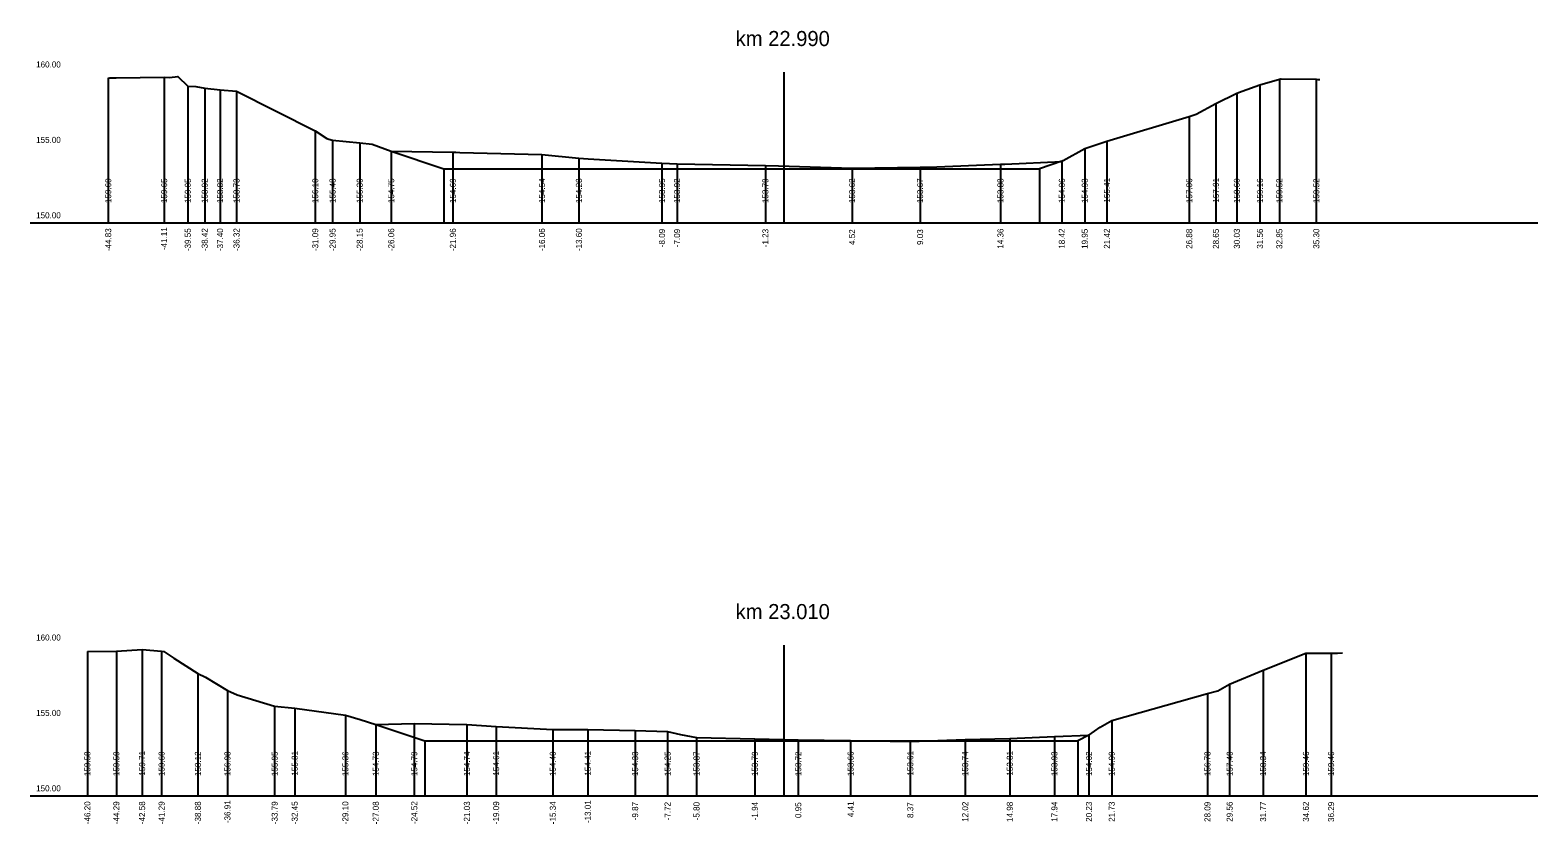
# Model space of a CAD drawing. Extents: x -582678 to -581845, y -1210354 to -1210235.
# Drawn here: x -582275.4 to -582175.4, y -1210306.7 to -1210254.1 of the extents above; entities that cross this region are included whole.
import ezdxf

# ---------------------------------------------------------------- set-up
doc = ezdxf.new("R2010")
doc.units = 0
for name, color, linetype in [('_N_osa', 7, 'Continuous'), ('_N_pomocná', 7, 'Continuous'), ('_N_tučná', 7, 'Continuous'), ('_S_popis', 7, 'Continuous'), ('_S_popis_oprav!', 7, 'Continuous'), ('_S_tenká', 7, 'Continuous'), ('_S_velmi_tenká', 7, 'Continuous')]:
    doc.layers.add(name, color=color, linetype=linetype)

msp = doc.modelspace()

# ---------------------------------------------------------------- linework, layer by layer
at = {"layer": '_N_osa'}
for p, q in [((-582225.45, -1210256.87), (-582225.45, -1210266.87)), ((-582225.45, -1210294.87), (-582225.45, -1210304.87))]:
    msp.add_line(p, q, dxfattribs=at)
at = {"layer": '_N_pomocná'}
for p, q in [((-582248, -1210263.29), (-582248, -1210266.87)), ((-582208.51, -1210263.29), (-582208.51, -1210266.87)), ((-582249.27, -1210301.23), (-582249.27, -1210304.87)), ((-582205.95, -1210301.23), (-582205.95, -1210304.87))]:
    msp.add_line(p, q, dxfattribs=at)
at = {"layer": '_N_tučná'}
for p, q in [((-582251.5, -1210262.12), (-582248, -1210263.29)), ((-582207.02, -1210262.79), (-582208.51, -1210263.29)), ((-582252.52, -1210300.14), (-582249.27, -1210301.23)), ((-582205.22, -1210300.85), (-582205.95, -1210301.23))]:
    msp.add_line(p, q, dxfattribs=at)
for points in [[(-582248, -1210263.29), (-582208.51, -1210263.29)], [(-582249.27, -1210301.23), (-582205.95, -1210301.23)]]:
    msp.add_lwpolyline(points, dxfattribs=at)
at = {"layer": '_S_tenká'}
for p, q in [((-582275.45, -1210266.87), (-582175.45, -1210266.87)), ((-582275.45, -1210304.87), (-582175.45, -1210304.87))]:
    msp.add_line(p, q, dxfattribs=at)
for points in [[(-582270.27, -1210257.27), (-582270.17, -1210257.26), (-582270.09, -1210257.26), (-582269.75, -1210257.26), (-582266.56, -1210257.22), (-582266.21, -1210257.24), (-582265.65, -1210257.17), (-582264.99, -1210257.81), (-582264.45, -1210257.83), (-582263.87, -1210257.95), (-582262.85, -1210258.05), (-582261.76, -1210258.14), (-582256.54, -1210260.77), (-582255.77, -1210261.28), (-582255.64, -1210261.32), (-582255.39, -1210261.39), (-582253.59, -1210261.57), (-582252.77, -1210261.65), (-582251.5, -1210262.12), (-582251.48, -1210262.13), (-582247.41, -1210262.18), (-582247.21, -1210262.18), (-582246.95, -1210262.2), (-582241.5, -1210262.33), (-582239.05, -1210262.59), (-582238.44, -1210262.62), (-582233.54, -1210262.92), (-582232.54, -1210262.95), (-582226.68, -1210263.08), (-582225.81, -1210263.1), (-582220.93, -1210263.25), (-582216.42, -1210263.19), (-582215.85, -1210263.18), (-582211.09, -1210262.99), (-582210.8, -1210262.98), (-582207.02, -1210262.81), (-582206.94, -1210262.74), (-582205.5, -1210261.94), (-582205.03, -1210261.78), (-582204.03, -1210261.46), (-582198.57, -1210259.81), (-582198.1, -1210259.67), (-582196.8, -1210258.96), (-582195.41, -1210258.27), (-582195.06, -1210258.15), (-582193.88, -1210257.71), (-582192.59, -1210257.35), (-582192.49, -1210257.32), (-582192.47, -1210257.32), (-582190.14, -1210257.35), (-582190.03, -1210257.36), (-582189.91, -1210257.36)], [(-582271.65, -1210295.29), (-582269.73, -1210295.28), (-582268.02, -1210295.16), (-582266.73, -1210295.27), (-582266.59, -1210295.3), (-582266.52, -1210295.34), (-582265.91, -1210295.75), (-582264.32, -1210296.75), (-582263.81, -1210297), (-582262.36, -1210297.89), (-582261.72, -1210298.17), (-582259.23, -1210298.92), (-582257.9, -1210299.06), (-582254.54, -1210299.51), (-582253.56, -1210299.81), (-582252.52, -1210300.14), (-582249.97, -1210300.08), (-582246.48, -1210300.13), (-582244.54, -1210300.26), (-582240.78, -1210300.47), (-582238.46, -1210300.46), (-582235.32, -1210300.54), (-582233.17, -1210300.61), (-582232.3, -1210300.8), (-582231.25, -1210300.99), (-582227.38, -1210301.08), (-582224.5, -1210301.15), (-582221.03, -1210301.21), (-582217.07, -1210301.26), (-582213.43, -1210301.13), (-582210.47, -1210301.06), (-582207.51, -1210300.93), (-582205.22, -1210300.85), (-582204.47, -1210300.32), (-582203.71, -1210299.88), (-582197.36, -1210298.09), (-582196.68, -1210297.9), (-582195.89, -1210297.47), (-582193.67, -1210296.53), (-582190.83, -1210295.4), (-582190.27, -1210295.4), (-582189.16, -1210295.4), (-582188.73, -1210295.4), (-582188.4, -1210295.39)]]:
    msp.add_lwpolyline(points, dxfattribs=at)
at = {"layer": '_S_velmi_tenká'}
for points in [[(-582270.27, -1210257.27), (-582270.27, -1210266.87), (-582270.27, -1210266.87), (-582270.27, -1210266.87)], [(-582266.56, -1210257.22), (-582266.56, -1210266.87), (-582266.56, -1210266.87), (-582266.56, -1210266.87)], [(-582264.99, -1210257.81), (-582264.99, -1210266.87), (-582264.99, -1210266.87), (-582264.99, -1210266.87)], [(-582263.87, -1210257.95), (-582263.87, -1210266.87), (-582263.87, -1210266.87), (-582263.87, -1210266.87)], [(-582193.88, -1210257.71), (-582193.88, -1210266.87), (-582193.88, -1210266.87), (-582193.88, -1210266.87)], [(-582192.59, -1210257.35), (-582192.59, -1210266.87), (-582192.59, -1210266.87), (-582192.59, -1210266.87)], [(-582190.14, -1210257.35), (-582190.14, -1210266.87), (-582190.14, -1210266.87), (-582190.14, -1210266.87)], [(-582262.85, -1210258.05), (-582262.85, -1210266.87), (-582262.85, -1210266.87), (-582262.85, -1210266.87)], [(-582261.76, -1210258.14), (-582261.76, -1210266.87), (-582261.76, -1210266.87), (-582261.76, -1210266.87)], [(-582196.8, -1210258.96), (-582196.8, -1210266.87), (-582196.8, -1210266.87), (-582196.8, -1210266.87)], [(-582195.41, -1210258.27), (-582195.41, -1210266.87), (-582195.41, -1210266.87), (-582195.41, -1210266.87)], [(-582198.57, -1210259.81), (-582198.57, -1210266.87), (-582198.57, -1210266.87), (-582198.57, -1210266.87)], [(-582256.54, -1210260.77), (-582256.54, -1210266.87), (-582256.54, -1210266.87), (-582256.54, -1210266.87)], [(-582255.39, -1210261.39), (-582255.39, -1210266.87), (-582255.39, -1210266.87), (-582255.39, -1210266.87)], [(-582253.59, -1210261.57), (-582253.59, -1210266.87), (-582253.59, -1210266.87), (-582253.59, -1210266.87)], [(-582205.5, -1210261.94), (-582205.5, -1210266.87), (-582205.5, -1210266.87), (-582205.5, -1210266.87)], [(-582204.03, -1210261.46), (-582204.03, -1210266.87), (-582204.03, -1210266.87), (-582204.03, -1210266.87)], [(-582251.5, -1210262.12), (-582251.5, -1210266.87), (-582251.5, -1210266.87), (-582251.5, -1210266.87)], [(-582247.41, -1210262.18), (-582247.41, -1210266.87), (-582247.41, -1210266.87), (-582247.41, -1210266.87)], [(-582241.5, -1210262.33), (-582241.5, -1210266.87), (-582241.5, -1210266.87), (-582241.5, -1210266.87)], [(-582239.05, -1210262.59), (-582239.05, -1210266.87), (-582239.05, -1210266.87), (-582239.05, -1210266.87)], [(-582233.54, -1210262.92), (-582233.54, -1210266.87), (-582233.54, -1210266.87), (-582233.54, -1210266.87)], [(-582232.54, -1210262.95), (-582232.54, -1210266.87), (-582232.54, -1210266.87), (-582232.54, -1210266.87)], [(-582211.09, -1210262.99), (-582211.09, -1210266.87), (-582211.09, -1210266.87), (-582211.09, -1210266.87)], [(-582207.02, -1210262.81), (-582207.02, -1210266.87), (-582207.02, -1210266.87), (-582207.02, -1210266.87)], [(-582226.68, -1210263.08), (-582226.68, -1210266.87), (-582226.68, -1210266.87), (-582226.68, -1210266.87)], [(-582220.93, -1210263.25), (-582220.93, -1210266.87), (-582220.93, -1210266.87), (-582220.93, -1210266.87)], [(-582216.42, -1210263.19), (-582216.42, -1210266.87), (-582216.42, -1210266.87), (-582216.42, -1210266.87)], [(-582271.65, -1210295.29), (-582271.65, -1210304.87), (-582271.65, -1210304.87), (-582271.65, -1210304.87)], [(-582269.73, -1210295.28), (-582269.73, -1210304.87), (-582269.73, -1210304.87), (-582269.73, -1210304.87)], [(-582268.02, -1210295.16), (-582268.02, -1210304.87), (-582268.02, -1210304.87), (-582268.02, -1210304.87)], [(-582266.73, -1210295.27), (-582266.73, -1210304.87), (-582266.73, -1210304.87), (-582266.73, -1210304.87)], [(-582190.83, -1210295.4), (-582190.83, -1210304.87), (-582190.83, -1210304.87), (-582190.83, -1210304.87)], [(-582189.16, -1210295.4), (-582189.16, -1210304.87), (-582189.16, -1210304.87), (-582189.16, -1210304.87)], [(-582264.32, -1210296.75), (-582264.32, -1210304.87), (-582264.32, -1210304.87), (-582264.32, -1210304.87)], [(-582193.67, -1210296.53), (-582193.67, -1210304.87), (-582193.67, -1210304.87), (-582193.67, -1210304.87)], [(-582262.36, -1210297.89), (-582262.36, -1210304.87), (-582262.36, -1210304.87), (-582262.36, -1210304.87)], [(-582195.89, -1210297.47), (-582195.89, -1210304.87), (-582195.89, -1210304.87), (-582195.89, -1210304.87)], [(-582259.23, -1210298.92), (-582259.23, -1210304.87), (-582259.23, -1210304.87), (-582259.23, -1210304.87)], [(-582197.36, -1210298.09), (-582197.36, -1210304.87), (-582197.36, -1210304.87), (-582197.36, -1210304.87)], [(-582257.9, -1210299.06), (-582257.9, -1210304.87), (-582257.9, -1210304.87), (-582257.9, -1210304.87)], [(-582254.54, -1210299.51), (-582254.54, -1210304.87), (-582254.54, -1210304.87), (-582254.54, -1210304.87)], [(-582203.71, -1210299.88), (-582203.71, -1210304.87), (-582203.71, -1210304.87), (-582203.71, -1210304.87)], [(-582252.52, -1210300.14), (-582252.52, -1210304.87), (-582252.52, -1210304.87), (-582252.52, -1210304.87)], [(-582249.97, -1210300.08), (-582249.97, -1210304.87), (-582249.97, -1210304.87), (-582249.97, -1210304.87)], [(-582246.48, -1210300.13), (-582246.48, -1210304.87), (-582246.48, -1210304.87), (-582246.48, -1210304.87)], [(-582244.54, -1210300.26), (-582244.54, -1210304.87), (-582244.54, -1210304.87), (-582244.54, -1210304.87)], [(-582240.78, -1210300.47), (-582240.78, -1210304.87), (-582240.78, -1210304.87), (-582240.78, -1210304.87)], [(-582238.46, -1210300.46), (-582238.46, -1210304.87), (-582238.46, -1210304.87), (-582238.46, -1210304.87)], [(-582235.32, -1210300.54), (-582235.32, -1210304.87), (-582235.32, -1210304.87), (-582235.32, -1210304.87)], [(-582233.17, -1210300.61), (-582233.17, -1210304.87), (-582233.17, -1210304.87), (-582233.17, -1210304.87)], [(-582231.25, -1210300.99), (-582231.25, -1210304.87), (-582231.25, -1210304.87), (-582231.25, -1210304.87)], [(-582207.51, -1210300.93), (-582207.51, -1210304.87), (-582207.51, -1210304.87), (-582207.51, -1210304.87)], [(-582205.22, -1210300.85), (-582205.22, -1210304.87), (-582205.22, -1210304.87), (-582205.22, -1210304.87)], [(-582227.38, -1210301.08), (-582227.38, -1210304.87), (-582227.38, -1210304.87), (-582227.38, -1210304.87)], [(-582224.5, -1210301.15), (-582224.5, -1210304.87), (-582224.5, -1210304.87), (-582224.5, -1210304.87)], [(-582221.03, -1210301.21), (-582221.03, -1210304.87), (-582221.03, -1210304.87), (-582221.03, -1210304.87)], [(-582217.07, -1210301.26), (-582217.07, -1210304.87), (-582217.07, -1210304.87), (-582217.07, -1210304.87)], [(-582213.43, -1210301.13), (-582213.43, -1210304.87), (-582213.43, -1210304.87), (-582213.43, -1210304.87)], [(-582210.47, -1210301.06), (-582210.47, -1210304.87), (-582210.47, -1210304.87), (-582210.47, -1210304.87)]]:
    msp.add_lwpolyline(points, dxfattribs=at)

# ---------------------------------------------------------------- texts
at = {"layer": '_S_popis'}
for s, p in [('160.00', (-582275.05, -1210256.57)), ('155.00', (-582275.05, -1210261.57)), ('150.00', (-582275.05, -1210266.57)), ('160.00', (-582275.05, -1210294.57)), ('155.00', (-582275.05, -1210299.57)), ('150.00', (-582275.05, -1210304.57))]:
    msp.add_text(s, height=0.4, dxfattribs=at).set_placement(p)
for s, p in [('159.60', (-582270.07, -1210265.56)), ('159.65', (-582266.36, -1210265.56)), ('159.05', (-582264.79, -1210265.56)), ('158.92', (-582263.67, -1210265.56)), ('158.82', (-582262.65, -1210265.56)), ('158.73', (-582261.56, -1210265.56)), ('156.10', (-582256.34, -1210265.56)), ('155.48', (-582255.19, -1210265.56)), ('155.30', (-582253.39, -1210265.56)), ('154.75', (-582251.3, -1210265.56)), ('154.69', (-582247.21, -1210265.56)), ('154.54', (-582241.3, -1210265.56)), ('154.28', (-582238.85, -1210265.56)), ('153.95', (-582233.34, -1210265.56)), ('153.92', (-582232.34, -1210265.56)), ('153.79', (-582226.48, -1210265.56)), ('153.62', (-582220.73, -1210265.56)), ('153.67', (-582216.22, -1210265.56)), ('153.88', (-582210.89, -1210265.56)), ('154.06', (-582206.82, -1210265.56)), ('154.93', (-582205.3, -1210265.56)), ('155.41', (-582203.83, -1210265.53)), ('157.06', (-582198.37, -1210265.56)), ('157.91', (-582196.6, -1210265.53)), ('158.60', (-582195.21, -1210265.56)), ('159.16', (-582193.68, -1210265.56)), ('159.52', (-582192.39, -1210265.56)), ('159.52', (-582189.94, -1210265.56)), ('-44.83', (-582270.07, -1210268.75)), ('-41.11', (-582266.36, -1210268.68)), ('-39.55', (-582264.79, -1210268.75)), ('-38.42', (-582263.67, -1210268.74)), ('-37.40', (-582262.65, -1210268.75)), ('-36.32', (-582261.56, -1210268.74)), ('-31.09', (-582256.34, -1210268.75)), ('-29.95', (-582255.19, -1210268.75)), ('-28.15', (-582253.39, -1210268.75)), ('-26.06', (-582251.3, -1210268.75)), ('-21.96', (-582247.21, -1210268.75)), ('-16.06', (-582241.3, -1210268.75)), ('-13.60', (-582238.85, -1210268.75)), ('-8.09', (-582233.34, -1210268.49)), ('-7.09', (-582232.34, -1210268.49)), ('-1.23', (-582226.48, -1210268.49)), ('4.52', (-582220.73, -1210268.34)), ('9.03', (-582216.22, -1210268.34)), ('14.36', (-582210.89, -1210268.59)), ('18.42', (-582206.82, -1210268.59)), ('19.95', (-582205.3, -1210268.6)), ('21.42', (-582203.83, -1210268.59)), ('26.88', (-582198.37, -1210268.6)), ('28.65', (-582196.6, -1210268.6)), ('30.03', (-582195.21, -1210268.59)), ('31.56', (-582193.68, -1210268.59)), ('32.85', (-582192.39, -1210268.6)), ('35.30', (-582189.94, -1210268.59)), ('159.58', (-582271.45, -1210303.56)), ('159.59', (-582269.53, -1210303.56)), ('159.71', (-582267.82, -1210303.53)), ('159.60', (-582266.53, -1210303.56)), ('158.12', (-582264.12, -1210303.56)), ('156.98', (-582262.16, -1210303.56)), ('155.95', (-582259.03, -1210303.56)), ('155.81', (-582257.7, -1210303.53)), ('155.36', (-582254.34, -1210303.56)), ('154.73', (-582252.32, -1210303.56)), ('154.79', (-582249.77, -1210303.56)), ('154.74', (-582246.28, -1210303.56)), ('154.61', (-582244.34, -1210303.53)), ('154.40', (-582240.58, -1210303.56)), ('154.41', (-582238.26, -1210303.53)), ('154.33', (-582235.12, -1210303.56)), ('154.25', (-582232.97, -1210303.56)), ('153.87', (-582231.05, -1210303.56)), ('153.79', (-582227.18, -1210303.56)), ('153.72', (-582224.3, -1210303.56)), ('153.66', (-582220.83, -1210303.56)), ('153.61', (-582216.87, -1210303.53)), ('153.74', (-582213.23, -1210303.56)), ('153.81', (-582210.27, -1210303.53)), ('153.93', (-582207.31, -1210303.56)), ('154.02', (-582205.02, -1210303.56)), ('154.99', (-582203.51, -1210303.56)), ('156.78', (-582197.16, -1210303.56)), ('157.40', (-582195.69, -1210303.56)), ('158.34', (-582193.47, -1210303.56)), ('159.46', (-582190.63, -1210303.56)), ('159.46', (-582188.96, -1210303.56)), ('-46.20', (-582271.45, -1210306.75)), ('-44.29', (-582269.53, -1210306.75)), ('-42.58', (-582267.82, -1210306.75)), ('-41.29', (-582266.53, -1210306.75)), ('-38.88', (-582264.12, -1210306.75)), ('-36.91', (-582262.16, -1210306.68)), ('-33.79', (-582259.03, -1210306.75)), ('-32.45', (-582257.7, -1210306.75)), ('-29.10', (-582254.34, -1210306.75)), ('-27.08', (-582252.32, -1210306.75)), ('-24.52', (-582249.77, -1210306.74)), ('-21.03', (-582246.28, -1210306.75)), ('-19.09', (-582244.34, -1210306.75)), ('-15.34', (-582240.58, -1210306.75)), ('-13.01', (-582238.26, -1210306.68)), ('-9.87', (-582235.12, -1210306.49)), ('-7.72', (-582232.97, -1210306.49)), ('-5.80', (-582231.05, -1210306.49)), ('-1.94', (-582227.18, -1210306.49)), ('0.95', (-582224.3, -1210306.34)), ('4.41', (-582220.83, -1210306.28)), ('8.37', (-582216.87, -1210306.34)), ('12.02', (-582213.23, -1210306.59)), ('14.98', (-582210.27, -1210306.6)), ('17.94', (-582207.31, -1210306.59)), ('20.23', (-582205.02, -1210306.59)), ('21.73', (-582203.51, -1210306.59)), ('28.09', (-582197.16, -1210306.6)), ('29.56', (-582195.69, -1210306.59)), ('31.77', (-582193.47, -1210306.59)), ('34.62', (-582190.63, -1210306.59)), ('36.29', (-582188.96, -1210306.6))]:
    msp.add_text(s, height=0.4, rotation=90, dxfattribs=at).set_placement(p)
at = {"layer": '_S_popis_oprav!'}
for s, p in [('km 22.990', (-582228.65, -1210255.15)), ('km 23.010', (-582228.65, -1210293.15))]:
    msp.add_text(s, height=1, dxfattribs=at).set_placement(p)

doc.saveas('drawing.dxf')
